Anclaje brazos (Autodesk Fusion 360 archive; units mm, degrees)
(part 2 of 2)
parameter "d_18_int" = 49 (= "d_18 - 3.5 mm")
parameter "d_19" = 49 (= "d_18_int")
parameter "d_19_int" = 45.5 (= "d_19 - 3.5 mm")
parameter "d_20" = 45.5 (= "d_19_int")
parameter "d_20_int" = 42 (= "d_20 - 3.5 mm")
parameter "d_21" = 42 (= "d_20_int")
parameter "d_21_int" = 38.5 (= "d_21 - 3.5 mm")
parameter "h_21" = 210
parameter "h_22" = 220
parameter "h_23" = 295
parameter "h_24" = 295
parameter "h_25" = 300
parameter "h_26" = 290
parameter "h_27" = 305
parameter "h_28" = 285
parameter "d_22" = 38.5 (= "d_21_int")
parameter "d_22_int" = 35 (= "d_22 - 3.5 mm")
parameter "d_23" = 35 (= "d_22_int")
parameter "d_23_int" = 31.5 (= "d_23 - 3.5 mm")
parameter "d_24" = 31.5 (= "d_23_int")
parameter "d_24_int" = 28 (= "d_24 - 3.5 mm")
parameter "d_25" = 28 (= "d_24_int")
parameter "d_25_int" = 24.5 (= "d_25 - 3.5 mm")
parameter "d_26" = 24.5 (= "d_25_int")
parameter "d_26_int" = 21 (= "d_26 - 3.5 mm")
parameter "d_27" = 21 (= "d_26_int")
parameter "d_27_int" = 17.5 (= "d_27 - 3.5 mm")
parameter "d_28" = 17.5 (= "d_27_int")
parameter "d_28_int" = 14 (= "d_28 - 3.5 mm")
parameter "d_29" = 14 (= "d_28_int")
parameter "d_29_int" = 10.5 (= "d_29 - 3.5 mm")
sketch "Boceto1" plane through (0, 0, 0) normal (0, 1, 0) x axis (1, 0, 0)
  circle C1 centre (0, 0) radius 56
  circle C2 centre (0, 0) radius 54.25
  point P1 (0, 0)
  point P2 (0, 0)
  coincident P1 P2
  concentric C1 C2
  dimension "d1" diameter C1 = 112 (= "d_1")
  dimension "d2" diameter C2 = 108.5 (= "d_1_int")
work_plane "PlanoDeObra2" AlongDistance -10 (= "h_1")
sketch "Boceto3" plane through (0, -10, 0) normal (0, 1, 0) x axis (1, 0, 0)
  circle C1 centre (0, 0) radius 54.25
  circle C2 centre (0, 0) radius 52.5
  point P1 (0, 0)
  point P2 (0, 0)
  coincident P1 P2
  concentric C1 C2
  dimension "d12" diameter C2 = 105 (= "d_2_int")
  dimension "d13" diameter C1 = 108.5 (= "d_2")
work_plane "PlanoDeObra3" AlongDistance 0
work_plane "PlanoDeObra4" AlongDistance 10 (= "h_2")
sketch "Boceto4" plane through (0, 10, 0) normal (0, 1, 0) x axis (1, 0, 0)
  circle C1 centre (0, 0) radius 52.5
  circle C2 centre (0, 0) radius 50.75
  point P1 (0, 0)
  point P2 (0, 0)
  point P3 (0, 0)
  coincident P1 P2
  coincident P1 P3
  dimension "d26" diameter C1 = 105 (= "d_3")
  dimension "d27" diameter C2 = 101.5 (= "d_3_int")
work_plane "PlanoDeObra5" AlongDistance -20 (= "h_3")
sketch "Boceto5" plane through (0, -20, 0) normal (0, 1, 0) x axis (1, 0, 0)
  circle C1 centre (0, 0) radius 50.75
  circle C2 centre (0, 0) radius 49
  point P1 (0, 0)
  point P2 (0, 0)
  point P3 (0, 0)
  coincident P1 P2
  coincident P1 P3
  dimension "d41" diameter C1 = 101.5 (= "d_4")
  dimension "d42" diameter C2 = 98 (= "d_4_int")
work_plane "PlanoDeObra6" AlongDistance 20 (= "h_4")
sketch "Boceto6" plane through (0, 20, 0) normal (0, 1, 0) x axis (1, 0, 0)
  circle C1 centre (0, 0) radius 49
  circle C2 centre (0, 0) radius 47.25
  point P1 (0, 0)
  point P2 (0, 0)
  coincident P1 P2
  concentric C1 C2
  dimension "d46" diameter C1 = 98 (= "d_5")
  dimension "d47" diameter C2 = 94.5 (= "d_5_int")
work_plane "PlanoDeObra7" AlongDistance -30 (= "h_5")
sketch "Boceto7" plane through (0, -30, 0) normal (0, 1, 0) x axis (1, 0, 0)
  circle C1 centre (0, 0) radius 47.25
  circle C2 centre (0, 0) radius 45.5
  point P1 (0, 0)
  point P2 (0, 0)
  coincident P1 P2
  concentric C1 C2
  dimension "d51" diameter C1 = 94.5 (= "d_6")
  dimension "d52" diameter C2 = 91 (= "d_6_int")
work_plane "PlanoDeObra8" AlongDistance 30 (= "h_6")
sketch "Boceto9" plane through (0, 30, 0) normal (0, 1, 0) x axis (1, 0, 0)
  circle C1 centre (0, 0) radius 45.5
  circle C2 centre (0, 0) radius 43.75
  point P1 (0, 0)
  point P2 (0, 0)
  point P3 (0, 0)
  coincident P1 P2
  coincident P1 P3
  dimension "d56" diameter C1 = 91 (= "d_7")
  dimension "d57" diameter C2 = 87.5 (= "d_7_int")
work_plane "PlanoDeObra9" AlongDistance 40 (= "h_7")
sketch "Boceto10" plane through (0, 40, 0) normal (0, 1, 0) x axis (1, 0, 0)
  circle C1 centre (0, 0) radius 43.75
  circle C2 centre (0, 0) radius 42
  point P1 (0, 0)
  point P2 (0, 0)
  coincident P1 P2
  concentric C1 C2
  dimension "d61" diameter C1 = 87.5 (= "d_8")
  dimension "d62" diameter C2 = 84 (= "d_8_int")
work_plane "PlanoDeObra10" AlongDistance 50 (= "h_8")
sketch "Boceto11" plane through (0, 50, 0) normal (0, 1, 0) x axis (1, 0, 0)
  circle C1 centre (0, 0) radius 42
  circle C2 centre (0, 0) radius 40.25
  point P1 (0, 0)
  point P2 (0, 0)
  coincident P1 P2
  concentric C1 C2
  dimension "d90" diameter C1 = 84 (= "d_9")
  dimension "d91" diameter C2 = 80.5 (= "d_9_int")
work_plane "PlanoDeObra11" AlongDistance 60 (= "h_9")
sketch "Boceto12" plane through (0, 60, 0) normal (0, 1, 0) x axis (1, 0, 0)
  circle C1 centre (0, 0) radius 40.25
  circle C2 centre (0, 0) radius 38.5
  point P1 (0, 0)
  point P2 (0, 0)
  point P3 (0, 0)
  coincident P1 P2
  coincident P1 P3
  dimension "d95" diameter C1 = 80.5 (= "d_10")
  dimension "d96" diameter C2 = 77 (= "d_10_int")
work_plane "PlanoDeObra12" AlongDistance 70 (= "h_10")
sketch "Boceto13" plane through (0, 70, 0) normal (0, 1, 0) x axis (1, 0, 0)
  circle C1 centre (0, 0) radius 38.5
  circle C2 centre (0, 0) radius 36.75
  point P1 (0, 0)
  point P2 (0, 0)
  point P3 (0, 0)
  coincident P1 P2
  coincident P1 P3
  dimension "d100" diameter C1 = 77 (= "d_11")
  dimension "d101" diameter C2 = 73.5 (= "d_11_int")
work_plane "PlanoDeObra13" AlongDistance 110 (= "h_11")
sketch "Boceto14" plane through (0, 110, 0) normal (0, 1, 0) x axis (1, 0, 0)
  circle C1 centre (0, 0) radius 36.75
  circle C2 centre (0, 0) radius 35
  point P1 (0, 0)
  point P2 (0, 0)
  coincident P1 P2
  concentric C1 C2
  dimension "d105" diameter C1 = 73.5 (= "d_12")
  dimension "d106" diameter C2 = 70 (= "d_12_int")
work_plane "PlanoDeObra14" AlongDistance 120 (= "h_12")
sketch "Boceto15" plane through (0, 120, 0) normal (0, 1, 0) x axis (1, 0, 0)
  circle C1 centre (0, 0) radius 35
  circle C2 centre (0, 0) radius 33.25
  point P1 (0, 0)
  point P2 (0, 0)
  coincident P1 P2
  concentric C1 C2
  dimension "d110" diameter C1 = 70 (= "d_13")
  dimension "d111" diameter C2 = 66.5 (= "d_13_int")
work_plane "PlanoDeObra15" AlongDistance 130 (= "h_13")
sketch "Boceto16" plane through (0, 130, 0) normal (0, 1, 0) x axis (1, 0, 0)
  circle C1 centre (0, 0) radius 33.25
  circle C2 centre (0, 0) radius 31.5
  point P1 (0, 0)
  point P2 (0, 0)
  coincident P1 P2
  concentric C1 C2
  dimension "d115" diameter C1 = 66.5 (= "d_14")
  dimension "d116" diameter C2 = 63 (= "d_14_int")
work_plane "PlanoDeObra17" AlongDistance 140 (= "h_14")
sketch "Boceto17" plane through (0, 140, 0) normal (0, 1, 0) x axis (1, 0, 0)
  circle C1 centre (0, 0) radius 31.5
  circle C2 centre (0, 0) radius 29.75
  point P1 (0, 0)
  point P2 (0, 0)
  point P3 (0, 0)
  coincident P1 P2
  coincident P1 P3
  dimension "d121" diameter C1 = 63 (= "d_15")
  dimension "d122" diameter C2 = 59.5 (= "d_15_int")
work_plane "PlanoDeObra18" AlongDistance 80 (= "h_15")
sketch "Boceto18" plane through (0, 80, 0) normal (0, 1, 0) x axis (1, 0, 0)
  circle C1 centre (0, 0) radius 29.75
  circle C2 centre (0, 0) radius 28
  point P1 (0, 0)
  point P2 (0, 0)
  point P3 (0, 0)
  coincident P1 P2
  coincident P1 P3
  dimension "d126" diameter C1 = 59.5 (= "d_16")
  dimension "d127" diameter C2 = 56 (= "d_16_int")
work_plane "PlanoDeObra19" AlongDistance 160 (= "h_16")
sketch "Boceto19" plane through (0, 160, 0) normal (0, 1, 0) x axis (1, 0, 0)
  circle C1 centre (0, 0) radius 28
  circle C2 centre (0, 0) radius 26.25
  point P1 (0, 0)
  point P2 (0, 0)
  coincident P1 P2
  concentric C1 C2
  dimension "d162" diameter C1 = 56 (= "d_17")
  dimension "d163" diameter C2 = 52.5 (= "d_17_int")
work_plane "PlanoDeObra20" AlongDistance 170 (= "h_17")
sketch "Boceto20" plane through (0, 170, 0) normal (0, 1, 0) x axis (1, 0, 0)
  circle C1 centre (0, 0) radius 26.25
  circle C2 centre (0, 0) radius 24.5
  point P1 (0, 0)
  point P2 (0, 0)
  coincident P1 P2
  concentric C1 C2
  dimension "d167" diameter C1 = 52.5 (= "d_18")
  dimension "d168" diameter C2 = 49 (= "d_18_int")
work_plane "PlanoDeObra21" AlongDistance 180 (= "h_18")
sketch "Boceto21" plane through (0, 180, 0) normal (0, 1, 0) x axis (1, 0, 0)
  circle C1 centre (0, 0) radius 24.5
  circle C2 centre (0, 0) radius 22.75
  point P1 (0, 0)
  point P2 (0, 0)
  point P3 (0, 0)
  coincident P1 P2
  coincident P1 P3
  dimension "d172" diameter C1 = 49 (= "d_19")
  dimension "d173" diameter C2 = 45.5 (= "d_19_int")
work_plane "PlanoDeObra22" AlongDistance 90 (= "h_19")
sketch "Boceto22" plane through (0, 90, 0) normal (0, 1, 0) x axis (1, 0, 0)
  circle C1 centre (0, 0) radius 22.75
  circle C2 centre (0, 0) radius 21
  point P1 (0, 0)
  point P2 (0, 0)
  point P3 (0, 0)
  coincident P1 P2
  coincident P1 P3
  dimension "d177" diameter C1 = 45.5 (= "d_20")
  dimension "d178" diameter C2 = 42 (= "d_20_int")
work_plane "PlanoDeObra24" AlongDistance 200 (= "h_20")
sketch "Boceto24" plane through (0, 200, 0) normal (0, 1, 0) x axis (1, 0, 0)
  circle C1 centre (0, 0) radius 21
  circle C2 centre (0, 0) radius 19.25
  point P1 (0, 0)
  point P2 (0, 0)
  point P3 (0, 0)
  coincident P1 P2
  coincident P1 P3
  dimension "d187" diameter C1 = 42 (= "d_21")
  dimension "d188" diameter C2 = 38.5 (= "d_21_int")
work_plane "PlanoDeObra25" AlongDistance 210 (= "h_21")
sketch "Boceto25" plane through (0, 210, 0) normal (0, 1, 0) x axis (1, 0, 0)
  circle C1 centre (0, 0) radius 19.25
  circle C2 centre (0, 0) radius 17.5
  point P1 (0, 0)
  point P2 (0, 0)
  coincident P1 P2
  concentric C1 C2
  dimension "d220" diameter C1 = 38.5 (= "d_22")
  dimension "d221" diameter C2 = 35 (= "d_22_int")
work_plane "PlanoDeObra26" AlongDistance 220 (= "h_22")
sketch "Boceto26" plane through (0, 220, 0) normal (0, 1, 0) x axis (1, 0, 0)
  circle C1 centre (0, 0) radius 17.5
  circle C2 centre (0, 0) radius 15.75
  point P1 (0, 0)
  point P2 (0, 0)
  coincident P1 P2
  concentric C1 C2
  dimension "d225" diameter C1 = 35 (= "d_23")
  dimension "d226" diameter C2 = 31.5 (= "d_23_int")
work_plane "PlanoDeObra28" AlongDistance 295 (= "h_23")
sketch "Boceto27" plane through (0, 295, 0) normal (0, 1, 0) x axis (1, 0, 0)
  circle C1 centre (0, 0) radius 15.75
  circle C2 centre (0, 0) radius 14
  point P1 (0, 0)
  point P2 (0, 0)
  coincident P1 P2
  concentric C1 C2
  dimension "d231" diameter C1 = 31.5 (= "d_24")
  dimension "d232" diameter C2 = 28 (= "d_24_int")
work_plane "PlanoDeObra29" AlongDistance 295 (= "h_24")
sketch "Boceto28" plane through (0, 295, 0) normal (0, 1, 0) x axis (1, 0, 0)
  circle C1 centre (0, 0) radius 14
  circle C2 centre (0, 0) radius 12.25
  point P1 (0, 0)
  point P2 (0, 0)
  point P3 (0, 0)
  coincident P1 P2
  coincident P1 P3
  dimension "d236" diameter C1 = 28 (= "d_25")
  dimension "d237" diameter C2 = 24.5 (= "d_25_int")
work_plane "PlanoDeObra30" AlongDistance 300 (= "h_25")
sketch "Boceto29" plane through (0, 300, 0) normal (0, 1, 0) x axis (1, 0, 0)
  circle C1 centre (0, 0) radius 12.25
  circle C2 centre (0, 0) radius 10.5
  point P1 (0, 0)
  point P2 (0, 0)
  coincident P1 P2
  concentric C1 C2
  dimension "d241" diameter C1 = 24.5 (= "d_26")
  dimension "d242" diameter C2 = 21 (= "d_26_int")
work_plane "PlanoDeObra31" AlongDistance 290 (= "h_26")
sketch "Boceto30" plane through (0, 290, 0) normal (0, 1, 0) x axis (1, 0, 0)
  circle C1 centre (0, 0) radius 10.5
  circle C2 centre (0, 0) radius 8.75
  point P1 (0, 0)
  point P2 (0, 0)
  point P3 (0, 0)
  coincident P1 P2
  coincident P1 P3
  dimension "d246" diameter C1 = 21 (= "d_27")
  dimension "d247" diameter C2 = 17.5 (= "d_27_int")
work_plane "PlanoDeObra32" AlongDistance 305 (= "h_27")
sketch "Boceto31" plane through (0, 305, 0) normal (0, 1, 0) x axis (1, 0, 0)
  circle C1 centre (0, 0) radius 8.75
  circle C2 centre (0, 0) radius 7
  point P1 (0, 0)
  point P2 (0, 0)
  coincident P1 P2
  concentric C1 C2
  dimension "d251" diameter C1 = 17.5 (= "d_28")
  dimension "d252" diameter C2 = 14 (= "d_28_int")
work_plane "PlanoDeObra33" AlongDistance 285 (= "h_28")
sketch "Boceto32" plane through (0, 285, 0) normal (0, 1, 0) x axis (1, 0, 0)
  circle C1 centre (0, 0) radius 7
  circle C2 centre (0, 0) radius 5.25
  point P1 (0, 0)
  point P2 (0, 0)
  coincident P1 P2
  concentric C1 C2
  dimension "d256" diameter C1 = 14 (= "d_29")
  dimension "d257" diameter C2 = 10.5 (= "d_29_int")
sketch "Boceto33" plane through (0, 0, 0) normal (0, 0, 1) x axis (1, 0, 0)
  line L1 (47.25, -30) -> (45.5, -30)
  line L2 (45.5, -27) -> (47.25, -27)
  line L3 (50.75, -20) -> (49, -20)
  line L4 (49, -17) -> (50.75, -17)
  line L5 (54.25, -10) -> (52.5, -10)
  line L6 (52.5, -7) -> (54.25, -7)
  line L7 (56, 0) -> (54.25, 0)
  line L8 (54.25, 3) -> (56, 3)
  line L9 (52.5, 10) -> (50.75, 10)
  line L10 (50.75, 13) -> (52.5, 13)
  line L11 (49, 20) -> (47.25, 20)
  line L12 (47.25, 23) -> (49, 23)
  line L13 (45.5, 30) -> (43.75, 30)
  line L14 (43.75, 33) -> (45.5, 33)
  line L15 (43.75, 40) -> (42, 40)
  line L16 (42, 43) -> (43.75, 43)
  line L17 (42, 50) -> (40.25, 50)
  line L18 (40.25, 53) -> (42, 53)
  line L19 (40.25, 60) -> (38.5, 60)
  line L20 (38.5, 63) -> (40.25, 63)
  line L21 (38.5, 70) -> (36.75, 70)
  line L22 (36.75, 73) -> (38.5, 73)
  line L23 (29.75, 80) -> (28, 80)
  line L24 (28, 83) -> (29.75, 83)
  line L25 (22.75, 90) -> (21, 90)
  line L26 (21, 93) -> (22.75, 93)
  line L27 (45.5, -30) -> (47.25, -30)
  line L28 (45.5, -27) -> (45.5, -30)
  line L29 (49, -20) -> (50.75, -20)
  line L30 (49, -17) -> (49, -20)
  line L31 (50.75, -17) -> (49, -17)
  line L32 (52.5, -10) -> (54.25, -10)
  line L33 (52.5, -10) -> (54.25, -10)
  line L34 (52.5, -7) -> (52.5, -10)
  line L35 (54.25, 0) -> (56, 0)
  line L36 (54.25, 0) -> (56, 0)
  line L37 (54.25, 3) -> (54.25, 0)
  line L38 (50.75, 10) -> (52.5, 10)
  line L39 (50.75, 13) -> (50.75, 10)
  line L40 (47.25, 20) -> (49, 20)
  line L41 (43.75, 30) -> (45.5, 30)
  line L42 (43.75, 33) -> (43.75, 30)
  line L43 (42, 40) -> (43.75, 40)
  line L44 (42, 43) -> (42, 40)
  line L45 (40.25, 50) -> (42, 50)
  line L46 (38.5, 60) -> (40.25, 60)
  line L47 (38.5, 63) -> (40.25, 63)
  line L48 (36.75, 70) -> (38.5, 70)
  line L49 (36.75, 73) -> (36.75, 70)
  line L50 (38.5, 60) -> (38.5, 63)
  line L51 (40.25, 53) -> (40.25, 50)
  line L52 (38.5, 73) -> (36.75, 75)
  line L53 (28, 80) -> (29.75, 80)
  line L54 (29.75, 83) -> (28, 85)
  line L55 (21, 90) -> (22.75, 90)
  line L56 (21, 93) -> (21, 90)
  line L57 (28, 83) -> (28, 80)
  line L58 (47.25, 23) -> (47.25, 20)
  line L59 (17, 88) -> (17, 90)
  line L60 (41.5, -32) -> (41.5, -25)
  line L61 (2, 90) -> (2, 95)
  line L62 (17, 90) -> (2, 90)
  line L63 (2, 100) -> (2, 95)
  line L64 (5, 100) -> (2, 100)
  line L65 (5, 96) -> (5, 100)
  line L66 (41.5, -37) -> (41.5, -32)
  line L67 (44.5, -37) -> (41.5, -37)
  line L68 (45.5, -37) -> (44.5, -37)
  line L69 (47.25, -38.2302) -> (47.25, -30)
  line L70 (47.25, -37) -> (45.5, -37)
  arc A1 centre (-131.6173, -3.3783) radius 174.4624 clockwise from (17, 88) to (41.5, -25)
  arc A2 centre (-12.1249, 48.1252) radius 54.4955 clockwise from (22.75, 90) to (29.75, 83)
  arc A3 centre (19.2917, 57.9584) radius 24.3969 clockwise from (29.75, 80) to (38.5, 73)
  arc A4 centre (-26.7489, 49.969) radius 68.2544 clockwise from (38.5, 70) to (40.25, 63)
  arc A5 centre (-76.2927, 27.1457) radius 121.0852 clockwise from (40.25, 60) to (42, 53)
  arc A6 centre (22.875, 41.5) radius 20.9289 clockwise from (42, 50) to (43.75, 43)
  arc A7 centre (-1.5, 24.9688) radius 47.6812 clockwise from (43.75, 40) to (45.5, 33)
  arc A8 centre (19.0393, 12.3947) radius 31.7823 clockwise from (45.5, 30) to (49, 23)
  arc A9 centre (-15.6248, -16.6874) radius 74.3124 clockwise from (49, 20) to (52.5, 13)
  arc A10 centre (40.625, -0.3125) radius 15.7278 clockwise from (52.5, 10) to (56, 3)
  arc A11 centre (21.7396, 4.8464) radius 34.6015 clockwise from (56, 0) to (54.25, -7)
  arc A12 centre (24.9327, 0.2836) radius 31.0686 clockwise from (54.25, -10) to (50.75, -17)
  arc A13 centre (-15.8334, 8.9167) radius 72.5915 clockwise from (50.75, -20) to (47.25, -27)
  arc A14 centre (4.1403, 36.9029) radius 59.1033 clockwise from (5, 96) to (22.75, 93)
  point P52 (28, 85)
  point P50 (36.75, 75)
  point P84 (47.25, -37)
  point P2 (47.25, -30)
  point P3 (47.25, -27)
  point P28 (45.5, -30)
  point P8 (56, 0)
  point P35 (54.25, 0)
  point P10 (52.5, 10)
  point P37 (50.75, 10)
  point P12 (49, 20)
  point P39 (47.25, 20)
  point P14 (45.5, 30)
  point P40 (43.75, 30)
  point P18 (42, 50)
  point P44 (40.25, 50)
  point P22 (38.5, 70)
  point P47 (36.75, 70)
  horizontal L1
  perpendicular L2 L28
  perpendicular L4 L30
  perpendicular L6 L34
  perpendicular L8 L37
  perpendicular L10 L39
  perpendicular L14 L42
  perpendicular L16 L44
  perpendicular L22 L49
  perpendicular L19 L50
  perpendicular L18 L51
  perpendicular L26 L56
  perpendicular L24 L57
  perpendicular L12 L58
  coincident P52 A2
  coincident P50 A3
  perpendicular L59 L62
  perpendicular L63 L64
  perpendicular L66 L67
  perpendicular L27 L69
  coincident L69 P84
  perpendicular L69 L70
  dimension "d262" distance P2 P3 = 3
  dimension "d263" distance P2 P28 = 1.75
  dimension "d272" distance P8 P35 = 1.75
  dimension "d275" distance P10 P37 = 1.75
  dimension "d280" distance P12 P39 = 1.75
  dimension "d285" distance P14 P40 = 1.75
  dimension "d288" distance P18 P44 = 1.75
  dimension "d291" distance P22 P47 = 1.75
sketch "Boceto34" plane through (0, 93, 0) normal (0, 1, 0) x axis (-1, 0, 0)
  line L1 (-185, 110) -> (-160, 110)
  line L2 (-160, 85) -> (-160, 110)
  line L3 (-135, 110) -> (-160, 110)
  line L4 (-160, 135) -> (-160, 110)
  line L5 (-184.8747, 107.5) -> (-160, 107.5)
  line L6 (-184.8747, 112.5) -> (-160, 112.5)
  line L7 (-162.5, 85.1253) -> (-162.5, 110)
  line L8 (-157.5, 85.1253) -> (-157.5, 110)
  line L9 (-135.1253, 107.5) -> (-160, 107.5)
  line L10 (-135.1253, 112.5) -> (-160, 112.5)
  line L11 (-162.5, 134.8747) -> (-162.5, 110)
  line L12 (-157.5, 134.8747) -> (-157.5, 110)
  circle C1 centre (-160, 110) radius 21
  circle C2 centre (-160, 110) radius 22.75
  circle C3 centre (-160, 110) radius 21
  circle C4 centre (-160, 110) radius 2.5
  circle C5 centre (-160, 110) radius 22.75
  circle C6 centre (-160, 110) radius 25
  point P6 (-160, 110)
  point P7 (-160, 110)
  point P8 (-185, 110)
  point P3 (-160, 110)
  point P9 (-160, 110)
  point P10 (-160, 85)
  point P5 (-160, 110)
  point P11 (-160, 110)
  point P12 (-135, 110)
  point P13 (-160, 135)
  point P14 (-160, 107.5)
  point P15 (-184.8747, 107.5)
  point P16 (-160, 112.5)
  point P17 (-184.8747, 112.5)
  point P18 (-162.5, 110)
  point P19 (-162.5, 85.1253)
  point P20 (-157.5, 110)
  point P21 (-157.5, 85.1253)
  point P22 (-135.1253, 107.5)
  point P23 (-135.1253, 112.5)
  point P24 (-162.5, 134.8747)
  point P25 (-157.5, 134.8747)
  tangent C1 C3
  concentric C3 C4
  concentric C4 C5
  concentric C4 C6
  coincident P6 P7
  coincident C6 P8
  horizontal L1
  coincident P3 P9
  coincident C6 P10
  perpendicular L1 L2
  coincident P5 P11
  coincident C6 P12
  perpendicular L2 L3
  coincident C6 P13
  perpendicular L3 L4
  coincident C4 P14
  coincident L2 P14
  coincident C6 P15
  tangent C4 L5
  coincident C4 P16
  coincident L4 P16
  coincident C6 P17
  tangent C4 L6
  coincident C4 P18
  coincident L1 P18
  coincident C6 P19
  tangent C4 L7
  coincident C4 P20
  coincident L3 P20
  coincident C6 P21
  tangent C4 L8
  coincident C6 P22
  horizontal L9
  coincident C6 P23
  parallel L9 L10
  coincident C6 P24
  perpendicular L10 L11
  coincident C6 P25
  vertical L12
  dimension "d294" diameter C4 = 5
  dimension "d297" diameter C6 = 50
extrude "Extruir" new body sketch "Boceto33" along normal blind 3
